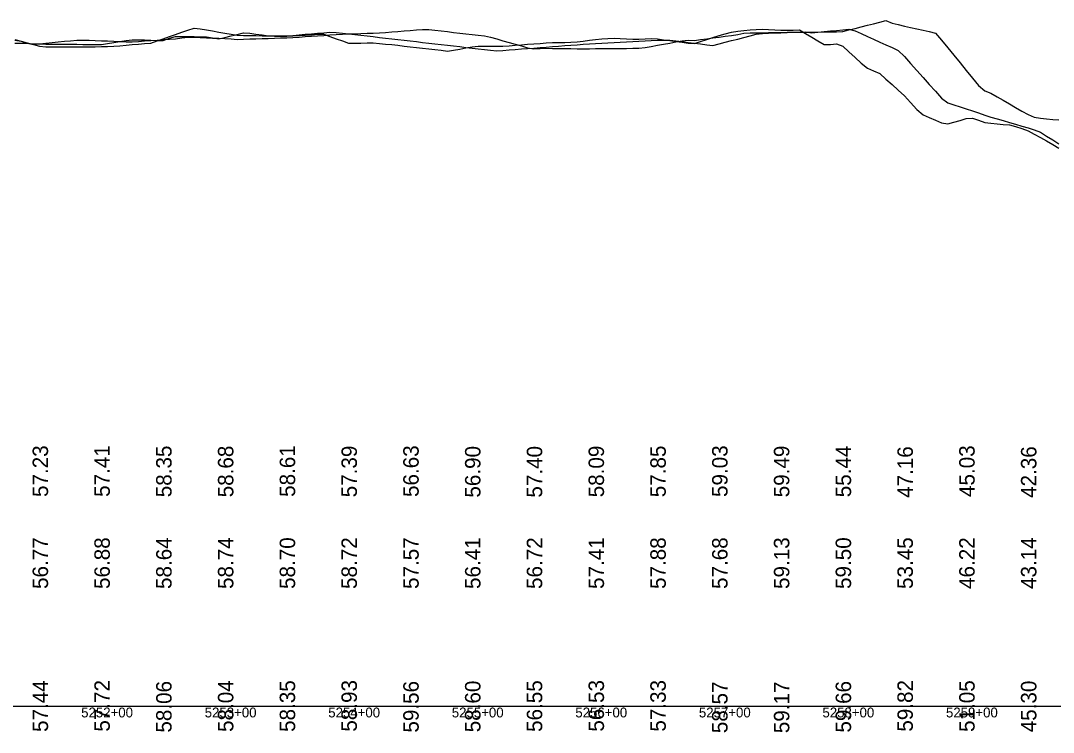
# Model space of a CAD drawing. Extents: x 2147288 to 2220488, y 740833 to 759333.
# Drawn here: x 2207508 to 2208344, y 750062 to 750639 of the extents above; entities that cross this region are included whole.
import ezdxf

# ---------------------------------------------------------------- set-up
doc = ezdxf.new("R2010")
doc.units = 0
for name, color, linetype in [('RD_DDB_Profile_EX', 7, 'Continuous'), ('RD_DDB_StaTX', 7, 'Continuous'), ('RD_DDB_StripGrade', 7, 'Continuous'), ('RD_GPK_Profile_Cell', 7, 'Continuous')]:
    doc.layers.add(name, color=color, linetype=linetype)

msp = doc.modelspace()

# ---------------------------------------------------------------- linework, layer by layer
at = {"layer": 'RD_DDB_Profile_EX'}
for points in [[(2207538.28, 750617.33), (2207543.28, 750617.37), (2207548.28, 750617.44), (2207553.28, 750617.49), (2207558.28, 750617.45), (2207563.28, 750617.42), (2207568.28, 750617.38), (2207573.28, 750617.53), (2207578.28, 750617.71), (2207583.28, 750617.89), (2207588.28, 750618.22), (2207593.28, 750618.68), (2207598.28, 750619.15), (2207603.28, 750619.61), (2207608.28, 750620.07), (2207613.28, 750620.4), (2207618.28, 750622.15), (2207623.28, 750623.91), (2207628.28, 750625.66), (2207633.28, 750627.41), (2207638.28, 750629.17), (2207643.28, 750630.92), (2207648.28, 750632.59), (2207653.28, 750631.93), (2207658.28, 750631.06), (2207663.28, 750630.2), (2207668.28, 750629.33), (2207673.28, 750628.47), (2207678.28, 750627.6), (2207683.28, 750626.74), (2207688.28, 750626.45), (2207693.28, 750626.43), (2207698.28, 750626.42), (2207703.28, 750626.4), (2207708.28, 750626.39), (2207713.28, 750626.38), (2207718.28, 750626.36), (2207723.28, 750626.35), (2207728.28, 750626.67), (2207733.28, 750627.09), (2207738.28, 750627.52), (2207743.28, 750627.94), (2207748.28, 750628.36), (2207753.28, 750628.79), (2207758.28, 750629.21), (2207763.28, 750629.07), (2207768.28, 750628.51), (2207773.28, 750627.93), (2207778.28, 750627.36), (2207783.28, 750626.78), (2207788.28, 750626.2), (2207793.28, 750625.62), (2207798.28, 750625.04), (2207803.28, 750624.47), (2207808.28, 750623.89), (2207813.28, 750623.31), (2207818.28, 750622.73), (2207823.28, 750622.15), (2207828.28, 750621.58), (2207833.28, 750621), (2207838.28, 750620.42), (2207843.28, 750619.84), (2207848.28, 750619.27), (2207853.28, 750618.69), (2207858.28, 750618.11), (2207863.28, 750617.53), (2207868.28, 750616.95), (2207873.28, 750616.38), (2207878.28, 750615.8), (2207883.28, 750615.22), (2207888.28, 750614.64), (2207893.28, 750614.06), (2207898.28, 750614.48), (2207903.28, 750614.87), (2207908.28, 750615.25), (2207913.28, 750615.64), (2207918.28, 750616.03), (2207923.28, 750616.42), (2207928.28, 750616.81), (2207933.28, 750617.2), (2207938.28, 750617.58), (2207943.28, 750617.97), (2207948.28, 750618.36), (2207953.28, 750618.75), (2207958.28, 750619.11), (2207963.28, 750619.42), (2207968.28, 750619.72), (2207973.28, 750620.03), (2207978.28, 750620.33), (2207983.28, 750620.63), (2207988.28, 750620.94), (2207993.28, 750621.24), (2207998.28, 750621.36), (2208003.28, 750621.62), (2208008.28, 750621.88), (2208013.28, 750622.13), (2208018.28, 750622.39), (2208023.28, 750622.64), (2208028.28, 750622.9), (2208033.28, 750622.8), (2208038.28, 750622.19)], [(2207538.28, 750621.35), (2207543.28, 750621.84), (2207548.28, 750622.33), (2207553.28, 750622.82), (2207558.28, 750622.89), (2207563.28, 750622.79), (2207568.28, 750622.57), (2207573.28, 750622.35), (2207578.28, 750622.13), (2207583.28, 750621.92), (2207588.28, 750621.7), (2207593.28, 750621.48), (2207598.28, 750621.45), (2207603.28, 750621.82), (2207608.28, 750622.17), (2207613.28, 750622.51), (2207618.28, 750622.86), (2207623.28, 750623.2), (2207628.28, 750623.55), (2207633.28, 750623.89), (2207638.28, 750624.69), (2207643.28, 750625.26), (2207648.28, 750625.07), (2207653.28, 750624.88), (2207658.28, 750624.7), (2207663.28, 750624.51), (2207668.28, 750624.32), (2207673.28, 750624.14), (2207678.28, 750623.84), (2207683.28, 750623.43), (2207688.28, 750623.59), (2207693.28, 750623.75), (2207698.28, 750623.91), (2207703.28, 750624.07), (2207708.28, 750624.24), (2207713.28, 750624.4), (2207718.28, 750624.56), (2207723.28, 750624.64), (2207728.28, 750624.98), (2207733.28, 750625.32), (2207738.28, 750625.66), (2207743.28, 750626), (2207748.28, 750626.34), (2207753.28, 750626.68), (2207758.28, 750627.02), (2207763.28, 750627.4), (2207768.28, 750627.59), (2207773.28, 750627.79), (2207778.28, 750627.98), (2207783.28, 750628.17), (2207788.28, 750628.37), (2207793.28, 750628.56), (2207798.28, 750628.75), (2207803.28, 750629.09), (2207808.28, 750629.48), (2207813.28, 750629.86), (2207818.28, 750630.25), (2207823.28, 750630.64), (2207828.28, 750631.03), (2207833.28, 750631.42), (2207838.28, 750631.43), (2207843.28, 750630.85), (2207848.28, 750630.27), (2207853.28, 750629.68), (2207858.28, 750629.1), (2207863.28, 750628.52), (2207868.28, 750627.94), (2207873.28, 750627.36), (2207878.28, 750626.78), (2207883.28, 750626.2), (2207888.28, 750625.19), (2207893.28, 750623.77), (2207898.28, 750622.35), (2207903.28, 750620.93), (2207908.28, 750619.51), (2207913.28, 750618.09), (2207918.28, 750616.67), (2207923.28, 750615.76), (2207928.28, 750616.14), (2207933.28, 750616.19), (2207938.28, 750616.12), (2207943.28, 750616.05), (2207948.28, 750615.98), (2207953.28, 750615.9), (2207958.28, 750615.83), (2207963.28, 750615.76), (2207968.28, 750615.88), (2207973.28, 750616.02), (2207978.28, 750616.05), (2207983.28, 750616.07), (2207988.28, 750616.1), (2207993.28, 750616.13), (2207998.28, 750616.15), (2208003.28, 750616.18), (2208008.28, 750616.32), (2208013.28, 750616.85), (2208018.28, 750617.76), (2208023.28, 750618.66), (2208028.28, 750619.57), (2208033.28, 750620.47), (2208038.28, 750621.37)], [(2208038.28, 750621.37), (2208043.28, 750622.28), (2208048.28, 750622.79), (2208053.28, 750622.61), (2208058.28, 750623.27), (2208063.28, 750623.93), (2208068.28, 750624.59), (2208073.28, 750625.25), (2208078.28, 750625.91), (2208083.28, 750626.57), (2208088.28, 750627.42), (2208093.28, 750628.53), (2208098.28, 750628.62), (2208103.28, 750628.72), (2208108.28, 750628.81), (2208113.28, 750628.9), (2208118.28, 750628.99), (2208123.28, 750629.08), (2208128.28, 750629.18), (2208133.28, 750629.36), (2208138.28, 750629.37), (2208143.28, 750629.37), (2208148.28, 750629.38), (2208153.28, 750629.38), (2208158.28, 750629.39), (2208163.28, 750629.39), (2208168.28, 750629.4), (2208173.28, 750629.85), (2208178.28, 750631.03), (2208183.28, 750632.29), (2208188.28, 750633.55), (2208193.28, 750634.8), (2208198.28, 750636.06), (2208203.28, 750637.32), (2208208.28, 750638.58), (2208213.28, 750636.56), (2208218.28, 750635.34), (2208223.28, 750634.24), (2208228.28, 750633.14), (2208233.28, 750632.04), (2208238.28, 750630.94), (2208243.28, 750629.84), (2208248.28, 750628.37), (2208253.28, 750622.77), (2208258.28, 750616.64), (2208263.28, 750610.5), (2208268.28, 750604.36), (2208273.28, 750598.23), (2208278.28, 750592.09), (2208283.28, 750585.95), (2208288.28, 750581.83), (2208293.28, 750579.84), (2208298.28, 750576.95), (2208303.28, 750574.07), (2208308.28, 750571.19), (2208313.28, 750568.3), (2208318.28, 750565.42), (2208323.28, 750562.54), (2208328.28, 750560.43), (2208333.28, 750559.55), (2208338.28, 750559.09), (2208343.28, 750558.64), (2208348.28, 750558.18)], [(2208038.28, 750622.19), (2208043.28, 750621.57), (2208048.28, 750620.96), (2208053.28, 750620.34), (2208058.28, 750619.73), (2208063.28, 750619.11), (2208068.28, 750618.49), (2208073.28, 750619.83), (2208078.28, 750621.12), (2208083.28, 750622.41), (2208088.28, 750623.7), (2208093.28, 750624.99), (2208098.28, 750626.28), (2208103.28, 750627.57), (2208108.28, 750628.26), (2208113.28, 750628.4), (2208118.28, 750628.59), (2208123.28, 750628.78), (2208128.28, 750628.96), (2208133.28, 750629.15), (2208138.28, 750629.33), (2208143.28, 750629.52), (2208148.28, 750628.75), (2208153.28, 750629.24), (2208158.28, 750629.72), (2208163.28, 750630.21), (2208168.28, 750630.7), (2208173.28, 750631.19), (2208178.28, 750631.67), (2208183.28, 750630.36), (2208188.28, 750628.09), (2208193.28, 750625.82), (2208198.28, 750623.55), (2208203.28, 750621.27), (2208208.28, 750619), (2208213.28, 750616.73), (2208218.28, 750614.46), (2208223.28, 750609.44), (2208228.28, 750603.82), (2208233.28, 750598.21), (2208238.28, 750592.6), (2208243.28, 750586.99), (2208248.28, 750581.38), (2208253.28, 750575.76), (2208258.28, 750572.01), (2208263.28, 750570.37), (2208268.28, 750568.73), (2208273.28, 750567.09), (2208278.28, 750565.45), (2208283.28, 750563.81), (2208288.28, 750562.17), (2208293.28, 750560.53), (2208298.28, 750559.08), (2208303.28, 750557.6), (2208308.28, 750556.12), (2208313.28, 750554.64), (2208318.28, 750553.15), (2208323.28, 750551.67), (2208328.28, 750550.19), (2208333.28, 750548.33), (2208338.28, 750545.16), (2208343.28, 750542), (2208348.28, 750538.84)], [(2208038.28, 750621.69), (2208043.28, 750621.05), (2208048.28, 750620.43), (2208053.28, 750619.95), (2208058.28, 750621.61), (2208063.28, 750623.28), (2208068.28, 750624.94), (2208073.28, 750626.58), (2208078.28, 750627.87), (2208083.28, 750629.16), (2208088.28, 750630.04), (2208093.28, 750630.53), (2208098.28, 750631.03), (2208103.28, 750631.53), (2208108.28, 750631.63), (2208113.28, 750631.37), (2208118.28, 750631.11), (2208123.28, 750630.85), (2208128.28, 750630.79), (2208133.28, 750630.98), (2208138.28, 750631.17), (2208143.28, 750628.16), (2208148.28, 750625.15), (2208153.28, 750622.14), (2208158.28, 750619.13), (2208163.28, 750619.24), (2208168.28, 750619.73), (2208173.28, 750617.8), (2208178.28, 750613.21), (2208183.28, 750608.62), (2208188.28, 750604.02), (2208193.28, 750600.23), (2208198.28, 750597.96), (2208203.28, 750595.68), (2208208.28, 750591.29), (2208213.28, 750586.79), (2208218.28, 750582.29), (2208223.28, 750577.79), (2208228.28, 750572.37), (2208233.28, 750566.75), (2208238.28, 750562.36), (2208243.28, 750560.19), (2208248.28, 750558.02), (2208253.28, 750555.85), (2208258.28, 750554.92), (2208263.28, 750556.37), (2208268.28, 750557.83), (2208273.28, 750559.28), (2208278.28, 750559.51), (2208283.28, 750557.87), (2208288.28, 750556.23), (2208293.28, 750555.54), (2208298.28, 750555.08), (2208303.28, 750554.62), (2208308.28, 750554.16), (2208313.28, 750552.77), (2208318.28, 750551.29), (2208323.28, 750549.48), (2208328.28, 750546.75), (2208333.28, 750544.02), (2208338.28, 750541.29), (2208343.28, 750538.39), (2208348.28, 750535.23)], [(2207503.28, 750623.31), (2207508.28, 750621.95), (2207513.28, 750620.58), (2207518.28, 750619.22), (2207523.28, 750617.86), (2207528.28, 750617.26), (2207533.28, 750617.3), (2207538.28, 750617.33)], [(2207503.28, 750622.87), (2207508.28, 750621.83), (2207513.28, 750620.47), (2207518.28, 750619.8), (2207523.28, 750619.7), (2207528.28, 750619.61), (2207533.28, 750619.52), (2207538.28, 750619.53)], [(2207538.28, 750619.53), (2207543.28, 750619.61), (2207548.28, 750619.52), (2207553.28, 750619.41), (2207558.28, 750619.31), (2207563.28, 750619.21), (2207568.28, 750619.17), (2207573.28, 750619.33), (2207578.28, 750620.02), (2207583.28, 750620.81), (2207588.28, 750621.59), (2207593.28, 750622.38), (2207598.28, 750622.92), (2207603.28, 750623.17), (2207608.28, 750622.95), (2207613.28, 750622.73), (2207618.28, 750622.51), (2207623.28, 750622.6), (2207628.28, 750624.35), (2207633.28, 750625.8), (2207638.28, 750625.74), (2207643.28, 750625.68), (2207648.28, 750625.61), (2207653.28, 750625.55), (2207658.28, 750625.44), (2207663.28, 750624.57), (2207668.28, 750623.74), (2207673.28, 750624.95), (2207678.28, 750626.16), (2207683.28, 750627.37), (2207688.28, 750628.58), (2207693.28, 750628.35), (2207698.28, 750627.67), (2207703.28, 750627), (2207708.28, 750626.33), (2207713.28, 750625.98), (2207718.28, 750625.96), (2207723.28, 750626.08), (2207728.28, 750626.34), (2207733.28, 750626.6), (2207738.28, 750626.86), (2207743.28, 750627.16), (2207748.28, 750627.58), (2207753.28, 750627.67), (2207758.28, 750625.82), (2207763.28, 750623.98), (2207768.28, 750622.14), (2207773.28, 750620.29), (2207778.28, 750620.35), (2207783.28, 750620.44), (2207788.28, 750620.54), (2207793.28, 750620.63), (2207798.28, 750620.19), (2207803.28, 750619.66), (2207808.28, 750619.13), (2207813.28, 750618.61), (2207818.28, 750618.05), (2207823.28, 750617.47), (2207828.28, 750616.89), (2207833.28, 750616.31), (2207838.28, 750615.73), (2207843.28, 750615.16), (2207848.28, 750614.58), (2207853.28, 750614), (2207858.28, 750614.59), (2207863.28, 750615.56), (2207868.28, 750616.52), (2207873.28, 750617.48), (2207878.28, 750617.92), (2207883.28, 750617.89), (2207888.28, 750617.87), (2207893.28, 750617.84), (2207898.28, 750617.97), (2207903.28, 750618.32), (2207908.28, 750618.68), (2207913.28, 750619.04), (2207918.28, 750619.41), (2207923.28, 750619.8), (2207928.28, 750620.19), (2207933.28, 750620.57), (2207938.28, 750620.8), (2207943.28, 750620.9), (2207948.28, 750621), (2207953.28, 750621.1), (2207958.28, 750621.46), (2207963.28, 750622.06), (2207968.28, 750622.67), (2207973.28, 750623.27), (2207978.28, 750623.72), (2207983.28, 750624.03), (2207988.28, 750624.29), (2207993.28, 750624.08), (2207998.28, 750623.87), (2208003.28, 750623.65), (2208008.28, 750623.49), (2208013.28, 750623.74), (2208018.28, 750624), (2208023.28, 750623.73), (2208028.28, 750623.05), (2208033.28, 750622.37), (2208038.28, 750621.69)], [(2207503.28, 750620.3), (2207508.28, 750620.3), (2207513.28, 750620.29), (2207518.28, 750619.38), (2207523.28, 750619.87), (2207528.28, 750620.36), (2207533.28, 750620.86), (2207538.28, 750621.35)]]:
    msp.add_lwpolyline(points, dxfattribs=at)
at = {"layer": 'RD_GPK_Profile_Cell'}
msp.add_line((2198888.28, 750083.43), (2220488.28, 750083.43), dxfattribs=at)

# ---------------------------------------------------------------- texts
at = {"layer": 'RD_DDB_Profile_EX'}
for s, p in [('57.23', (2207530.08, 750252.89)), ('57.41', (2207580.08, 750253)), ('58.35', (2207630.08, 750252.69)), ('58.68', (2207680.08, 750252.64)), ('58.61', (2207730.08, 750253)), ('57.39', (2207780.08, 750252.64)), ('56.63', (2207830.08, 750252.89)), ('56.90', (2207880.08, 750252.38)), ('57.40', (2207930.08, 750252.38)), ('58.09', (2207980.08, 750252.64)), ('57.85', (2208030.08, 750252.69)), ('59.03', (2208080.08, 750252.89)), ('59.49', (2208130.08, 750252.64)), ('55.44', (2208180.08, 750252.66)), ('47.16', (2208230.08, 750252.13)), ('45.03', (2208280.08, 750252.89)), ('42.36', (2208330.08, 750252.13)), ('57.44', (2207530.08, 750062.66)), ('57.72', (2207580.08, 750062.89)), ('58.06', (2207630.08, 750062.13)), ('58.04', (2207680.08, 750062.66)), ('58.35', (2207730.08, 750062.69)), ('58.93', (2207780.08, 750062.89)), ('59.56', (2207830.08, 750062.13)), ('58.60', (2207880.08, 750062.38)), ('56.55', (2207930.08, 750062.69)), ('56.53', (2207980.08, 750062.89)), ('57.33', (2208030.08, 750062.89)), ('58.57', (2208080.08, 750061.67)), ('59.17', (2208130.08, 750061.67)), ('59.66', (2208180.08, 750062.13)), ('59.82', (2208230.08, 750062.89)), ('51.05', (2208280.08, 750062.69)), ('45.30', (2208330.08, 750062.38))]:
    msp.add_text(s, height=12.5, rotation=90, dxfattribs=at).set_placement(p)
at = {"layer": 'RD_DDB_StaTX'}
for s, p in [('5252+00', (2207556.88, 750074.43)), ('5252+00', (2207556.88, 750074.43)), ('5252+00', (2207556.88, 750074.43)), ('5253+00', (2207656.88, 750074.43)), ('5253+00', (2207656.88, 750074.43)), ('5253+00', (2207656.88, 750074.43)), ('5254+00', (2207756.88, 750074.43)), ('5254+00', (2207756.88, 750074.43)), ('5254+00', (2207756.88, 750074.43)), ('5255+00', (2207856.88, 750074.43)), ('5255+00', (2207856.88, 750074.43)), ('5255+00', (2207856.88, 750074.43)), ('5256+00', (2207956.88, 750074.43)), ('5256+00', (2207956.88, 750074.43)), ('5256+00', (2207956.88, 750074.43)), ('5257+00', (2208056.88, 750074.43)), ('5257+00', (2208056.88, 750074.43)), ('5257+00', (2208056.88, 750074.43)), ('5258+00', (2208156.88, 750074.43)), ('5258+00', (2208156.88, 750074.43)), ('5258+00', (2208156.88, 750074.43)), ('5259+00', (2208256.88, 750074.43)), ('5259+00', (2208256.88, 750074.43)), ('5259+00', (2208256.88, 750074.43))]:
    msp.add_text(s, height=8, dxfattribs=at).set_placement(p)
at = {"layer": 'RD_DDB_StripGrade'}
for s, p in [('56.77', (2207530.08, 750178.43)), ('56.88', (2207580.08, 750178.43)), ('58.64', (2207630.08, 750178.43)), ('58.74', (2207680.08, 750178.43)), ('58.70', (2207730.08, 750178.43)), ('58.72', (2207780.08, 750178.43)), ('57.57', (2207830.08, 750178.43)), ('56.41', (2207880.08, 750178.43)), ('56.72', (2207930.08, 750178.43)), ('57.41', (2207980.08, 750178.43)), ('57.88', (2208030.08, 750178.43)), ('57.68', (2208080.08, 750178.43)), ('59.13', (2208130.08, 750178.43)), ('59.50', (2208180.08, 750178.43)), ('53.45', (2208230.08, 750178.43)), ('46.22', (2208280.08, 750178.43)), ('43.14', (2208330.08, 750178.43))]:
    msp.add_text(s, height=12.5, rotation=90, dxfattribs=at).set_placement(p)

doc.saveas('drawing.dxf')
